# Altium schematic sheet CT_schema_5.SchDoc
size 298 x 247 mm
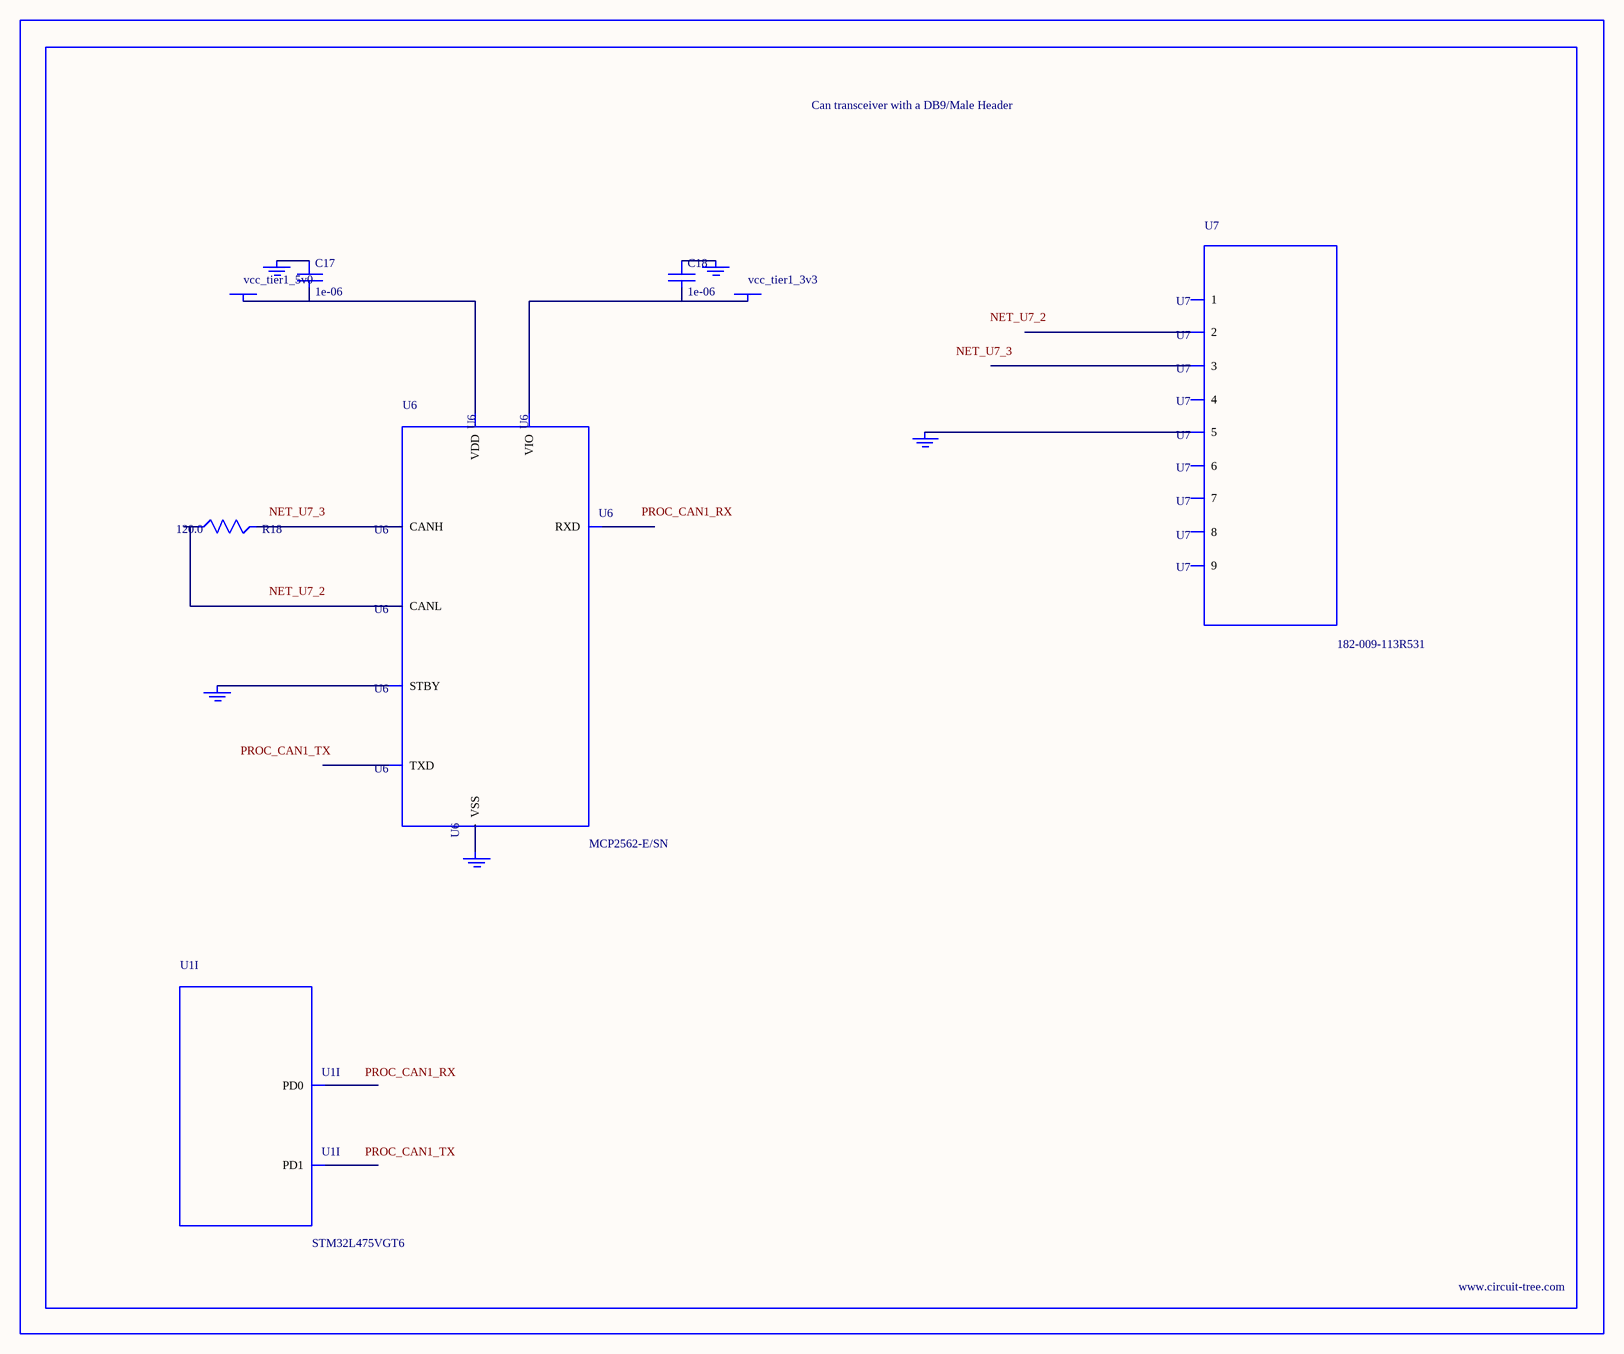
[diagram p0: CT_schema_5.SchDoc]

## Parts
BORDER4  (no value)
C17  1e-06  [C0603]
C18  1e-06  [C0603]
GND_INSTANCE_4_0  (no value)
GND_INSTANCE_4_1  (no value)
GND_INSTANCE_4_2  (no value)
GND_INSTANCE_4_3  (no value)
GND_INSTANCE_4_4  (no value)
POWER_INSTANCE_4_0  vcc_tier1_5v0
POWER_INSTANCE_4_1  vcc_tier1_3v3
R18  120.0  [R0603]
U1  STM32L475VGT6  [LQFP100]  (part I of 11)
U6  MCP2562-E/SN  [SOIC-8]
U7  182-009-113R531  [182-009-MALE]

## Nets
NetC17_1: C17.1 GND_INSTANCE_4_0.0(GND)
NetC17_2: C17.2 POWER_INSTANCE_4_0.0(PWR) U6.3(VDD)
NetC18_1: C18.1 GND_INSTANCE_4_1.0(GND)
NetC18_2: C18.2 POWER_INSTANCE_4_1.0(PWR) U6.5(VIO)
NetGND_INSTANCE_4_2_0: GND_INSTANCE_4_2.0(GND) U6.8(STBY)
NetGND_INSTANCE_4_3_0: GND_INSTANCE_4_3.0(GND) U6.2(VSS)
NetGND_INSTANCE_4_4_0: GND_INSTANCE_4_4.0(GND) U7.5
NetR18_1: R18.1 U6.6(CANL)
NetR18_2: R18.2 U6.7(CANH)

Not connected (* = marked no-connect by the designer): U1 81(PD0) 82(PD1); U6 1(TXD) 4(RXD); U7 1 2 3 4 6 7 8 9

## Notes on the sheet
- Labels drawn without touching a wire or pin: NET_U7_2, NET_U7_3, PROC_CAN1_RX, PROC_CAN1_TX

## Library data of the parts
BORDER4 = BORDER_PAGE4
C17 C18 = C0603C105K3RACTU
GND_INSTANCE_4_0-GND_INSTANCE_4_4 = GND
POWER_INSTANCE_4_0 POWER_INSTANCE_4_1 = PWR
R18 = RC0603JR-07120RL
